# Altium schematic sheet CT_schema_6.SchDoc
size 278 x 170 mm
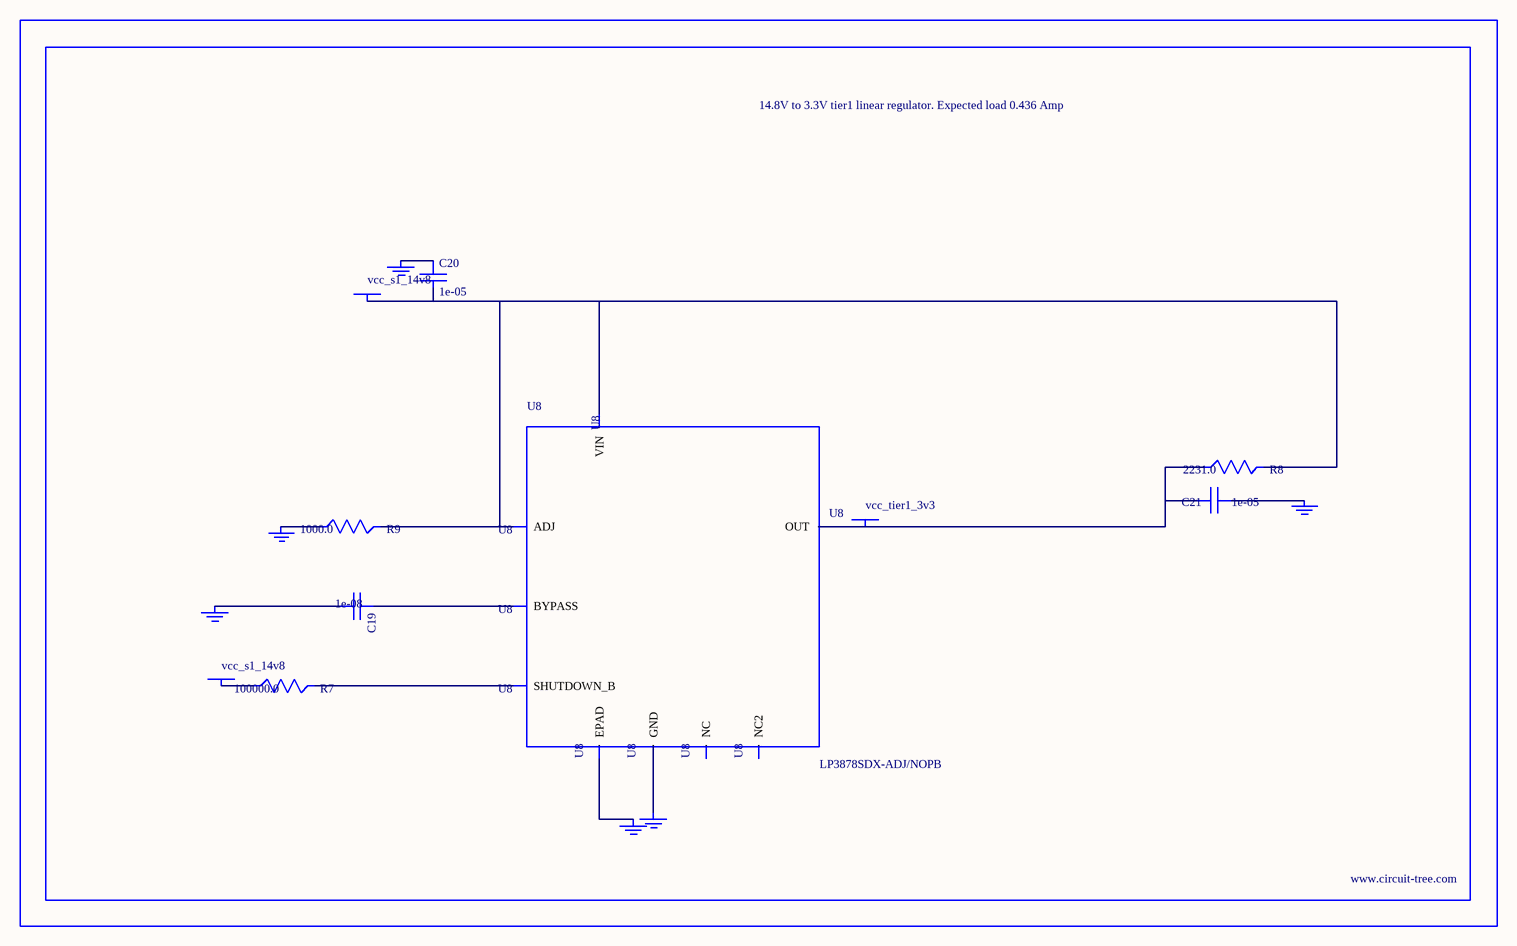
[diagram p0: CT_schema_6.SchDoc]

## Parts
BORDER5  (no value)
C19  1e-08  [C0402]
C20  1e-05  [C1210]
C21  1e-05  [C1210]
GND_INSTANCE_5_0  (no value)
GND_INSTANCE_5_1  (no value)
GND_INSTANCE_5_2  (no value)
GND_INSTANCE_5_3  (no value)
GND_INSTANCE_5_4  (no value)
GND_INSTANCE_5_5  (no value)
POWER_INSTANCE_5_0  vcc_s1_14v8
POWER_INSTANCE_5_1  vcc_s1_14v8
POWER_INSTANCE_5_2  vcc_tier1_3v3
R7  100000.0  [R0603]
R8  2231.0  [R0603]
R9  1000.0  [R0603]
U8  LP3878SDX-ADJ/NOPB  [WSON-8]

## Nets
NetC19_1: C19.1 U8.1(BYPASS)
NetC19_2: C19.2 GND_INSTANCE_5_0.0(GND)
NetC20_1: C20.1 GND_INSTANCE_5_1.0(GND)
NetC20_2: C20.2 POWER_INSTANCE_5_0.0(PWR) R8.2 R9.2 U8.4(VIN) U8.6(ADJ)
NetC21_1: C21.1 GND_INSTANCE_5_2.0(GND)
NetC21_2: C21.2 POWER_INSTANCE_5_2.0(PWR) R8.1 U8.5(OUT)
NetGND_INSTANCE_5_3_0: GND_INSTANCE_5_3.0(GND) R9.1
NetGND_INSTANCE_5_4_0: GND_INSTANCE_5_4.0(GND) U8.PAD(EPAD)
NetGND_INSTANCE_5_5_0: GND_INSTANCE_5_5.0(GND) U8.3(GND)
NetPOWER_INSTANCE_5_1_0: POWER_INSTANCE_5_1.0(PWR) R7.1
NetR7_2: R7.2 U8.8(SHUTDOWN_B)

Not connected (* = marked no-connect by the designer): U8 2(NC) 7(NC2)

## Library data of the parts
BORDER5 = BORDER_PAGE5
C19 = C0402C103K3RAC
C20 = C1210C106K5PACTU
C21 = GRM32DR61E106MA12L
GND_INSTANCE_5_0-GND_INSTANCE_5_5 = GND
POWER_INSTANCE_5_0-POWER_INSTANCE_5_2 = PWR
R7 = RC0603JR-07100KL
R8 = R8
R9 = RC0603JR-071KL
